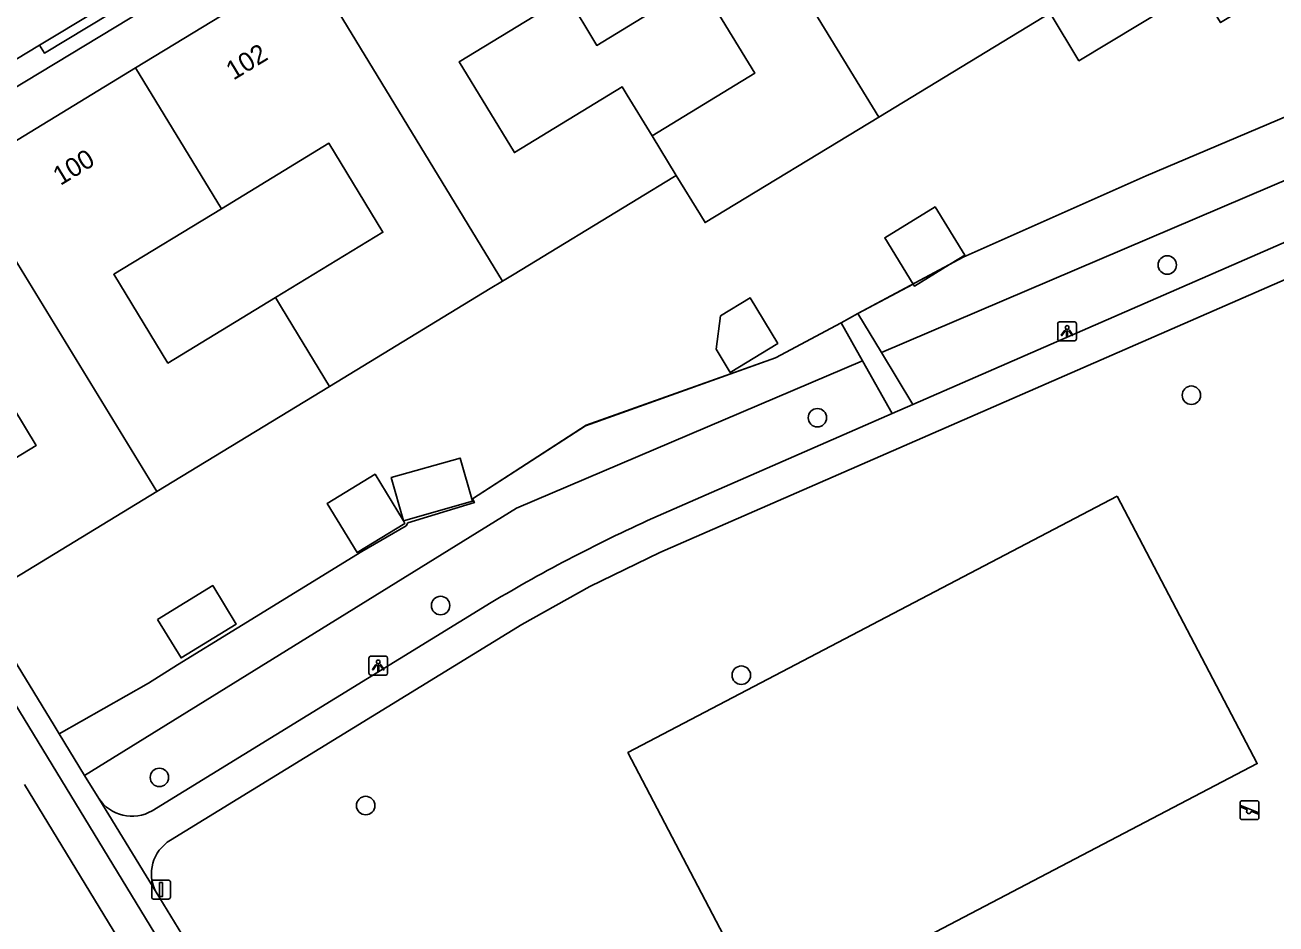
# Model space of a CAD drawing. Extents: x 157767 to 159171, y 387842 to 389425.
# Drawn here: x 158182.2 to 158248.5, y 388524.5 to 388572.1 of the extents above; entities that cross this region are included whole.
import ezdxf

# ---------------------------------------------------------------- set-up
doc = ezdxf.new("R2010")
doc.units = 0
for name, color, linetype in [('IMGEO_Boom', 7, 'Continuous'), ('IMGEO_Groenvoorziening', 7, 'Continuous'), ('IMGEO_Hek', 7, 'Continuous'), ('IMGEO_Lichtpunt', 7, 'Continuous'), ('IMGEO_Pand', 7, 'Continuous'), ('IMGEO_Pand_nummerreeks', 7, 'Continuous'), ('IMGEO_Rijbaan_lokaal_open', 7, 'Continuous'), ('IMGEO_Speelvoorziening', 7, 'Continuous'), ('IMGEO_Verkeersbordpaal', 7, 'Continuous'), ('IMGEO_Voetpad_halfverhard', 7, 'Continuous'), ('IMGEO_Voetpad_open', 7, 'Continuous')]:
    doc.layers.add(name, color=color, linetype=linetype)

msp = doc.modelspace()

# ---------------------------------------------------------------- linework, layer by layer
at = {"layer": 'IMGEO_Boom'}
for centre in [(158242.741, 388559.418), (158244.022, 388552.516), (158224.197, 388551.323), (158204.221, 388541.368), (158220.162, 388537.675), (158189.314, 388532.256), (158200.251, 388530.765)]:
    msp.add_circle(centre, 0.489, dxfattribs=at)
at = {"layer": 'IMGEO_Groenvoorziening'}
for points in [[(158258.921, 388571.504), (158251.842, 388568.481), (158241.624, 388564.137), (158231.921, 388559.825), (158231.207, 388559.442)], [(158227.593, 388554.774), (158263.591, 388570.127)], [(158229.273, 388558.406), (158226.348, 388556.838)], [(158184.003, 388534.564), (158188.744, 388537.244), (158190.273, 388538.217), (158193.432, 388540.174), (158200.041, 388544.235), (158202.393, 388545.599), (158202.487, 388545.748), (158206.018, 388546.823), (158205.91, 388547.014), (158211.91, 388550.892), (158221.981, 388554.498), (158225.452, 388556.358)], [(158226.59, 388554.346), (158208.25, 388546.524), (158185.347, 388532.366)], [(158240.087, 388547.161), (158247.513, 388532.988), (158221.577, 388519.398), (158214.151, 388533.571), (158240.087, 388547.161)]]:
    msp.add_lwpolyline(points, dxfattribs=at)
at = {"layer": 'IMGEO_Hek'}
for points in [[(158226.348, 388556.838), (158231.921, 388559.825), (158241.624, 388564.137), (158251.842, 388568.481), (158258.921, 388571.504)], [(158225.452, 388556.358), (158226.348, 388556.838)], [(158184.003, 388534.564), (158188.744, 388537.244), (158190.273, 388538.217), (158193.432, 388540.174), (158200.041, 388544.235), (158202.393, 388545.599), (158202.487, 388545.748), (158206.018, 388546.823), (158205.91, 388547.014), (158211.947, 388550.933), (158221.981, 388554.498), (158225.452, 388556.358)]]:
    msp.add_lwpolyline(points, dxfattribs=at)
at = {"layer": 'IMGEO_Lichtpunt'}
for p, q in [((158236.933, 388556.305), (158236.933, 388555.498)), ((158236.933, 388556.305), (158236.933, 388555.498)), ((158237.835, 388556.4), (158237.027, 388556.4)), ((158237.835, 388556.4), (158237.027, 388556.4)), ((158237.929, 388555.498), (158237.929, 388556.305)), ((158237.929, 388555.498), (158237.929, 388556.305)), ((158237.027, 388555.404), (158237.835, 388555.404)), ((158237.027, 388555.404), (158237.835, 388555.404)), ((158200.417, 388538.582), (158200.417, 388537.775)), ((158200.417, 388538.582), (158200.417, 388537.775)), ((158201.319, 388538.677), (158200.511, 388538.677)), ((158201.319, 388538.677), (158200.511, 388538.677)), ((158201.413, 388537.775), (158201.413, 388538.582)), ((158201.413, 388537.775), (158201.413, 388538.582)), ((158200.511, 388537.681), (158201.319, 388537.681)), ((158200.511, 388537.681), (158201.319, 388537.681))]:
    msp.add_line(p, q, dxfattribs=at)
for points in [[(158237.307, 388555.969), (158237.346, 388555.941), (158237.158, 388555.679), (158237.12, 388555.706), (158237.307, 388555.969)], [(158237.409, 388555.921), (158237.456, 388555.921), (158237.456, 388555.599), (158237.409, 388555.599), (158237.409, 388555.921)], [(158237.519, 388555.941), (158237.557, 388555.968), (158237.744, 388555.706), (158237.705, 388555.678), (158237.519, 388555.941)], [(158200.791, 388538.246), (158200.83, 388538.218), (158200.642, 388537.956), (158200.604, 388537.983), (158200.791, 388538.246)], [(158200.893, 388538.198), (158200.94, 388538.198), (158200.94, 388537.876), (158200.893, 388537.876), (158200.893, 388538.198)], [(158201.003, 388538.218), (158201.041, 388538.245), (158201.228, 388537.983), (158201.189, 388537.955), (158201.003, 388538.218)]]:
    msp.add_lwpolyline(points, dxfattribs=at)
for centre in [(158237.432, 388556.103), (158200.916, 388538.38)]:
    msp.add_circle(centre, 0.0994, dxfattribs=at)
for centre, start, end in [((158237.027, 388556.305), 90, 180), ((158237.027, 388556.305), 90, 180), ((158237.835, 388556.305), 0, 90), ((158237.835, 388556.305), 0, 90), ((158237.027, 388555.498), 180, 270), ((158237.027, 388555.498), 180, 270), ((158237.835, 388555.498), 270, 0), ((158237.835, 388555.498), 270, 360), ((158200.511, 388538.582), 90, 180), ((158200.511, 388538.582), 90, 180), ((158201.319, 388538.582), 0, 90), ((158201.319, 388538.582), 0, 90), ((158200.511, 388537.775), 180, 270), ((158200.511, 388537.775), 180, 270), ((158201.319, 388537.775), 270, 0), ((158201.319, 388537.775), 270, 360)]:
    msp.add_arc(centre, 0.0946, start, end, dxfattribs=at)
at = {"layer": 'IMGEO_Pand'}
for points in [[(158217.133, 388584.101), (158227.455, 388567.248)], [(158188.055, 388569.869), (158197.217, 388575.446)], [(158197.217, 388575.446), (158207.497, 388558.559)], [(158247.35, 388575.864), (158248.464, 388574.04), (158245.566, 388572.27), (158244.445, 388574.106), (158238.058, 388570.24), (158236.531, 388572.771)], [(158215.436, 388566.257), (158220.887, 388569.59), (158217.954, 388574.388), (158212.502, 388571.055), (158210.93, 388573.681)], [(158210.93, 388573.681), (158205.201, 388570.178), (158208.135, 388565.379), (158213.84, 388568.867), (158214.115, 388568.417), (158215.436, 388566.257)], [(158236.531, 388572.771), (158236.196, 388572.568), (158227.455, 388567.248)], [(158178.863, 388564.275), (158188.055, 388569.869)], [(158188.055, 388569.869), (158192.6, 388562.401)], [(158227.455, 388567.248), (158218.24, 388561.67), (158217.992, 388562.076), (158216.712, 388564.168)], [(158215.436, 388566.257), (158216.712, 388564.168)], [(158195.469, 388557.688), (158201.166, 388561.155), (158198.297, 388565.868), (158192.6, 388562.401)], [(158189.174, 388547.407), (158184.104, 388544.321), (158179.832, 388541.721), (158177.018, 388546.344), (158182.79, 388549.858), (158179.836, 388554.712), (158174.043, 388551.186), (158169.533, 388558.596), (158178.863, 388564.275)], [(158189.174, 388547.407), (158178.863, 388564.275)], [(158216.712, 388564.168), (158216.541, 388564.064), (158214.672, 388562.926), (158208.122, 388558.939), (158207.497, 388558.559)], [(158192.6, 388562.401), (158186.898, 388558.93), (158189.766, 388554.218), (158195.469, 388557.688)], [(158231.207, 388559.442), (158232.008, 388559.933), (158230.436, 388562.5), (158227.766, 388560.865), (158229.273, 388558.406)], [(158231.207, 388559.442), (158229.339, 388558.298), (158229.273, 388558.406)], [(158207.497, 388558.559), (158206.855, 388558.168), (158198.333, 388552.982)], [(158195.469, 388557.688), (158195.729, 388557.26), (158196.088, 388556.671), (158198.333, 388552.982)], [(158218.822, 388554.961), (158219.573, 388553.727), (158222.097, 388555.264), (158220.628, 388557.678), (158219.052, 388556.719), (158218.822, 388554.961)], [(158198.333, 388552.982), (158189.174, 388547.407)], [(158202.25, 388545.861), (158205.913, 388546.893), (158205.267, 388549.186), (158201.604, 388548.153), (158202.25, 388545.861)], [(158202.25, 388545.861), (158200.75, 388548.325), (158198.213, 388546.781), (158199.796, 388544.18), (158202.333, 388545.724), (158202.25, 388545.861)], [(158189.215, 388540.634), (158190.463, 388538.591), (158193.389, 388540.38), (158192.141, 388542.423), (158189.215, 388540.634)]]:
    msp.add_lwpolyline(points, dxfattribs=at)
at = {"layer": 'IMGEO_Rijbaan_lokaal_open'}
msp.add_lwpolyline([(158205.044, 388494.546), (158204.926, 388494.49), (158201.572, 388500), (158182.164, 388531.882)], dxfattribs=at)
at = {"layer": 'IMGEO_Speelvoorziening'}
for p, q in [((158246.608, 388530.118), (158246.608, 388530.918)), ((158246.608, 388530.918), (158246.608, 388530.118)), ((158246.708, 388531.018), (158247.498, 388531.018)), ((158247.498, 388531.018), (158246.708, 388531.018)), ((158247.598, 388530.918), (158247.598, 388530.118)), ((158247.598, 388530.118), (158247.598, 388530.918)), ((158246.991, 388530.546), (158246.652, 388530.683)), ((158246.677, 388530.743), (158247.553, 388530.39)), ((158247.529, 388530.33), (158247.189, 388530.467)), ((158247.498, 388530.018), (158246.708, 388530.018)), ((158246.708, 388530.018), (158247.498, 388530.018))]:
    msp.add_line(p, q, dxfattribs=at)
for centre, radius, start, end in [((158246.708, 388530.918), 0.1, 90, 180), ((158246.708, 388530.918), 0.1, 90, 180), ((158247.498, 388530.918), 0.1, 0, 90), ((158247.498, 388530.918), 0.1, 360, 90), ((158246.708, 388530.118), 0.1, 180, 270), ((158246.708, 388530.118), 0.1, 180, 270), ((158246.665, 388530.713), 0.0327, 68.07798, 248.07798), ((158247.07, 388530.456), 0.12, 130.99278, 5.16318), ((158247.498, 388530.118), 0.1, 270, 0), ((158247.498, 388530.118), 0.1, 270, 0), ((158247.541, 388530.36), 0.0327, 248.07798, 68.07798)]:
    msp.add_arc(centre, radius, start, end, dxfattribs=at)
at = {"layer": 'IMGEO_Verkeersbordpaal'}
for p, q in [((158189.009, 388526.811), (158189.799, 388526.811)), ((158189.799, 388526.811), (158189.009, 388526.811)), ((158188.909, 388525.911), (158188.909, 388526.711)), ((158188.909, 388526.711), (158188.909, 388525.911)), ((158189.899, 388526.711), (158189.899, 388525.911)), ((158189.899, 388525.911), (158189.899, 388526.711)), ((158189.799, 388525.811), (158189.009, 388525.811)), ((158189.009, 388525.811), (158189.799, 388525.811))]:
    msp.add_line(p, q, dxfattribs=at)
msp.add_lwpolyline([(158189.329, 388526.686), (158189.479, 388526.686), (158189.479, 388525.936), (158189.329, 388525.936), (158189.329, 388526.686)], dxfattribs=at)
for centre, start, end in [((158189.009, 388526.711), 90, 180), ((158189.009, 388526.711), 90, 180), ((158189.799, 388526.711), 0, 90), ((158189.799, 388526.711), 360, 90), ((158189.009, 388525.911), 180, 270), ((158189.009, 388525.911), 180, 270), ((158189.799, 388525.911), 270, 0), ((158189.799, 388525.911), 270, 0)]:
    msp.add_arc(centre, 0.1, start, end, dxfattribs=at)
at = {"layer": 'IMGEO_Voetpad_halfverhard'}
for points in [[(158260.821, 388565.785), (158229.255, 388552.015)], [(158189.907, 388528.931), (158208.535, 388540.365), (158212.134, 388542.381), (158215.85, 388544.172), (158258.461, 388562.778)], [(158228.166, 388551.539), (158215.752, 388546.124)], [(158206.896, 388541.52), (158188.927, 388530.484)]]:
    msp.add_lwpolyline(points, dxfattribs=at)
for centre, radius, start, end in [((158250.444, 388468.574), 84.956, 114.10104, 120.83642), ((158187.861, 388532.316), 2.12, 213.69651, 300.2019), ((158190.963, 388527.148), 2.072, 120.64841, 208.25633)]:
    msp.add_arc(centre, radius, start, end, dxfattribs=at)
at = {"layer": 'IMGEO_Voetpad_open'}
for points in [[(158246.138, 388598.786), (158197.753, 388577.86), (158190.887, 388574.405), (158170.328, 388561.976)], [(158188.802, 388574.609), (158189.06, 388574.182), (158183.219, 388570.647), (158182.961, 388571.074)], [(158182.961, 388571.074), (158188.802, 388574.609)], [(158182.961, 388571.074), (158173.489, 388565.342)], [(158169.401, 388558.443), (158173.894, 388551.095), (158176.859, 388546.247), (158183.73, 388535.011), (158184.003, 388534.564)], [(158225.452, 388556.358), (158226.348, 388556.838)], [(158226.348, 388556.838), (158227.593, 388554.774)], [(158225.452, 388556.358), (158226.59, 388554.346)], [(158170.254, 388554.863), (158203.669, 388500), (158205.312, 388497.303)], [(158227.593, 388554.774), (158229.255, 388552.015)], [(158228.166, 388551.539), (158226.59, 388554.346)], [(158229.255, 388552.015), (158228.166, 388551.539)], [(158185.347, 388532.366), (158184.003, 388534.564)], [(158185.347, 388532.366), (158186.097, 388531.14)], [(158186.097, 388531.14), (158189.138, 388526.167)], [(158189.138, 388526.167), (158191.278, 388522.668)]]:
    msp.add_lwpolyline(points, dxfattribs=at)

# ---------------------------------------------------------------- texts
at = {"layer": 'IMGEO_Pand_nummerreeks'}
for s, p in [('102', (158193.24, 388569.187)), ('100', (158184.068, 388563.604))]:
    msp.add_text(s, height=1, rotation=31.32933, dxfattribs=at).set_placement(p)

doc.saveas('drawing.dxf')
